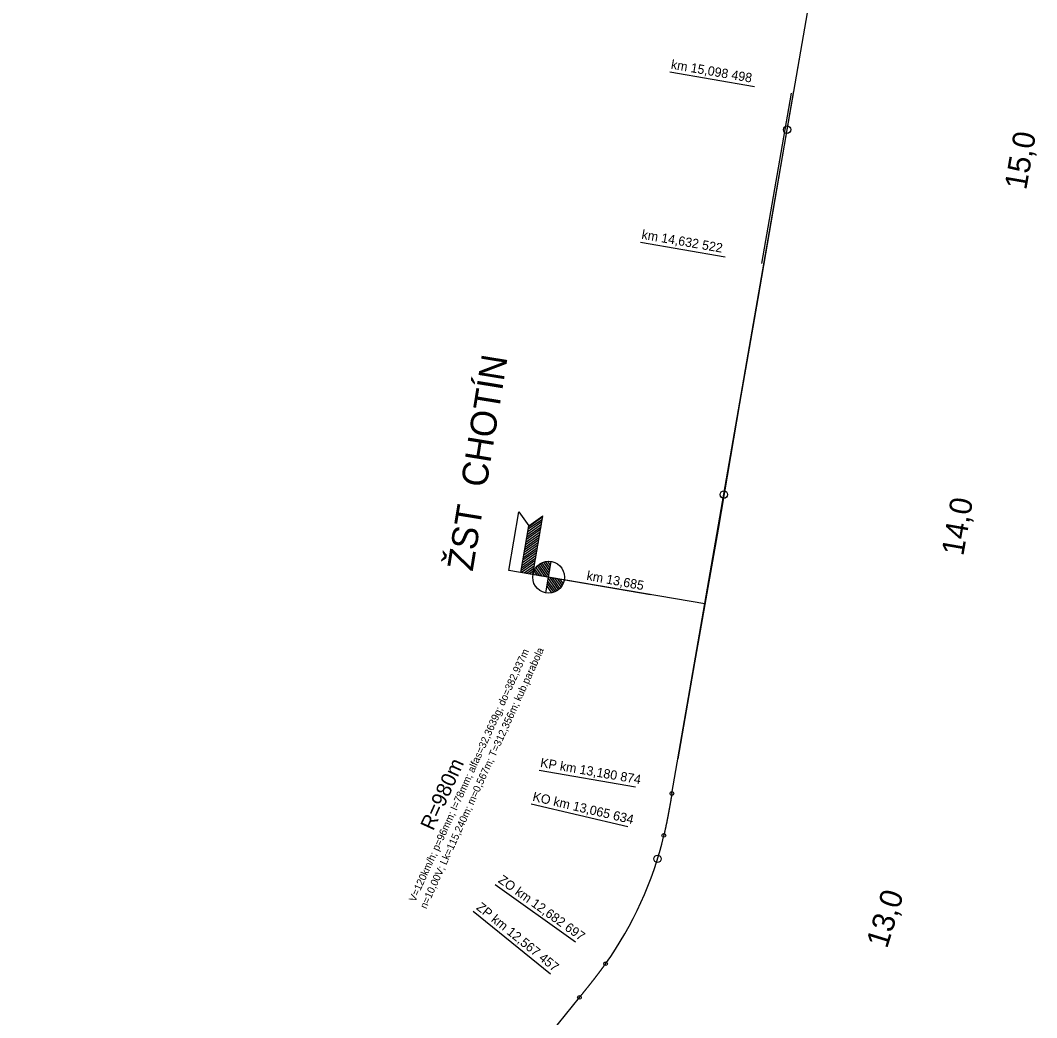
# Model space of a CAD drawing. Extents: x -504999 to -493096, y -1330712 to -1305226.
# Drawn here: x -498638 to -495893, y -1326629 to -1323937 of the extents above; entities that cross this region are included whole.
import ezdxf

# ---------------------------------------------------------------- set-up
doc = ezdxf.new("R2010")
doc.units = 0
for name, color, linetype in [('0_HM', 7, 'Continuous'), ('0_obluky', 7, 'Continuous'), ('0_popis oblukov', 7, 'Continuous'), ('0_STANICE', 7, 'Continuous'), ('0_stanicenie oblukov', 7, 'Continuous'), ('dotyčnice', 7, 'Continuous'), ('Level 1', 7, 'Continuous'), ('PHS', 7, 'Continuous')]:
    doc.layers.add(name, color=color, linetype=linetype)

msp = doc.modelspace()

# ---------------------------------------------------------------- linework, layer by layer
at = {"layer": '0_HM'}
for centre in [(-496567.3, -1324232), (-496738.3, -1325217.3), (-496917.3, -1326200.8)]:
    msp.add_circle(centre, 10, dxfattribs=at)
at = {"layer": '0_obluky'}
for p, q in [((-496878.3, -1326024.3), (-496328.8, -1322856.9)), ((-498638, -1328441.5), (-497128.1, -1326574.9))]:
    msp.add_line(p, q, dxfattribs=at)
for points in [[(-496878.3, -1326024.3), (-496878.5, -1326025.3), (-496878.6, -1326026.3), (-496878.8, -1326027.3), (-496879, -1326028.3), (-496879.1, -1326029.3), (-496879.3, -1326030.3), (-496879.5, -1326031.2), (-496879.7, -1326032.2), (-496879.8, -1326033.2), (-496880, -1326034.2), (-496880.2, -1326035.2), (-496880.3, -1326036.2), (-496880.5, -1326037.2), (-496880.7, -1326038.2), (-496880.9, -1326039.1), (-496881, -1326040.1), (-496881.2, -1326041.1), (-496881.4, -1326042.1), (-496881.6, -1326043.1), (-496881.7, -1326044.1), (-496881.9, -1326045.1), (-496882.1, -1326046.1), (-496882.2, -1326047), (-496882.4, -1326048), (-496882.6, -1326049), (-496882.8, -1326050), (-496882.9, -1326051), (-496883.1, -1326052), (-496883.3, -1326053), (-496883.5, -1326053.9), (-496883.6, -1326054.9), (-496883.8, -1326055.9), (-496884, -1326056.9), (-496884.2, -1326057.9), (-496884.3, -1326058.9), (-496884.5, -1326059.9), (-496884.7, -1326060.8), (-496884.9, -1326061.8), (-496885.1, -1326062.8), (-496885.2, -1326063.8), (-496885.4, -1326064.8), (-496885.6, -1326065.8), (-496885.8, -1326066.8), (-496885.9, -1326067.7), (-496886.1, -1326068.7), (-496886.3, -1326069.7), (-496886.5, -1326070.7), (-496886.7, -1326071.7), (-496886.9, -1326072.7), (-496887, -1326073.7), (-496887.2, -1326074.6), (-496887.4, -1326075.6), (-496887.6, -1326076.6), (-496887.8, -1326077.6), (-496887.9, -1326078.6), (-496888.1, -1326079.6), (-496888.3, -1326080.6), (-496888.5, -1326081.5), (-496888.7, -1326082.5), (-496888.9, -1326083.5), (-496889.1, -1326084.5), (-496889.3, -1326085.5), (-496889.4, -1326086.5), (-496889.6, -1326087.4), (-496889.8, -1326088.4), (-496890, -1326089.4), (-496890.2, -1326090.4), (-496890.4, -1326091.4), (-496890.6, -1326092.4), (-496890.8, -1326093.3), (-496891, -1326094.3), (-496891.2, -1326095.3), (-496891.4, -1326096.3), (-496891.6, -1326097.3), (-496891.7, -1326098.3), (-496891.9, -1326099.2), (-496892.1, -1326100.2), (-496892.3, -1326101.2), (-496892.5, -1326102.2), (-496892.7, -1326103.2), (-496892.9, -1326104.2), (-496893.1, -1326105.1), (-496893.3, -1326106.1), (-496893.5, -1326107.1), (-496893.7, -1326108.1), (-496893.9, -1326109.1), (-496894.1, -1326110), (-496894.4, -1326111), (-496894.6, -1326112), (-496894.8, -1326113), (-496895, -1326114), (-496895.2, -1326114.9), (-496895.4, -1326115.9), (-496895.6, -1326116.9), (-496895.8, -1326117.9), (-496896, -1326118.9), (-496896.2, -1326119.8), (-496896.4, -1326120.8), (-496896.7, -1326121.8), (-496896.9, -1326122.8), (-496897.1, -1326123.8), (-496897.3, -1326124.7), (-496897.5, -1326125.7), (-496897.7, -1326126.7), (-496898, -1326127.7), (-496898.2, -1326128.7), (-496898.4, -1326129.6), (-496898.6, -1326130.6), (-496898.8, -1326131.6), (-496899.1, -1326132.6), (-496899.3, -1326133.5), (-496899.5, -1326134.5), (-496899.8, -1326135.5), (-496900, -1326136.5), (-496900.2, -1326137.5)], [(-497128.1, -1326574.9), (-497127.5, -1326574.2), (-497126.9, -1326573.4), (-497126.2, -1326572.6), (-497125.6, -1326571.8), (-497125, -1326571.1), (-497124.3, -1326570.3), (-497123.7, -1326569.5), (-497123.1, -1326568.7), (-497122.5, -1326567.9), (-497121.8, -1326567.2), (-497121.2, -1326566.4), (-497120.6, -1326565.6), (-497119.9, -1326564.8), (-497119.3, -1326564), (-497118.7, -1326563.3), (-497118, -1326562.5), (-497117.4, -1326561.7), (-497116.8, -1326560.9), (-497116.2, -1326560.1), (-497115.5, -1326559.4), (-497114.9, -1326558.6), (-497114.3, -1326557.8), (-497113.6, -1326557), (-497113, -1326556.2), (-497112.4, -1326555.5), (-497111.8, -1326554.7), (-497111.1, -1326553.9), (-497110.5, -1326553.1), (-497109.9, -1326552.3), (-497109.3, -1326551.6), (-497108.6, -1326550.8), (-497108, -1326550), (-497107.4, -1326549.2), (-497106.7, -1326548.4), (-497106.1, -1326547.6), (-497105.5, -1326546.9), (-497104.9, -1326546.1), (-497104.2, -1326545.3), (-497103.6, -1326544.5), (-497103, -1326543.7), (-497102.4, -1326543), (-497101.7, -1326542.2), (-497101.1, -1326541.4), (-497100.5, -1326540.6), (-497099.9, -1326539.8), (-497099.3, -1326539), (-497098.6, -1326538.2), (-497098, -1326537.5), (-497097.4, -1326536.7), (-497096.8, -1326535.9), (-497096.1, -1326535.1), (-497095.5, -1326534.3), (-497094.9, -1326533.5), (-497094.3, -1326532.7), (-497093.7, -1326532), (-497093, -1326531.2), (-497092.4, -1326530.4), (-497091.8, -1326529.6), (-497091.2, -1326528.8), (-497090.6, -1326528), (-497090, -1326527.2), (-497089.3, -1326526.4), (-497088.7, -1326525.6), (-497088.1, -1326524.9), (-497087.5, -1326524.1), (-497086.9, -1326523.3), (-497086.3, -1326522.5), (-497085.6, -1326521.7), (-497085, -1326520.9), (-497084.4, -1326520.1), (-497083.8, -1326519.3), (-497083.2, -1326518.5), (-497082.6, -1326517.7), (-497082, -1326516.9), (-497081.4, -1326516.1), (-497080.8, -1326515.3), (-497080.1, -1326514.6), (-497079.5, -1326513.8), (-497078.9, -1326513), (-497078.3, -1326512.2), (-497077.7, -1326511.4), (-497077.1, -1326510.6), (-497076.5, -1326509.8), (-497075.9, -1326509), (-497075.3, -1326508.2), (-497074.7, -1326507.4), (-497074.1, -1326506.6), (-497073.5, -1326505.8), (-497072.9, -1326505), (-497072.3, -1326504.2), (-497071.7, -1326503.4), (-497071.1, -1326502.6), (-497070.5, -1326501.8), (-497069.9, -1326501), (-497069.3, -1326500.2), (-497068.7, -1326499.4), (-497068.1, -1326498.5), (-497067.5, -1326497.7), (-497066.9, -1326496.9), (-497066.3, -1326496.1), (-497065.7, -1326495.3), (-497065.1, -1326494.5), (-497064.5, -1326493.7), (-497063.9, -1326492.9), (-497063.3, -1326492.1), (-497062.7, -1326491.3), (-497062.1, -1326490.5), (-497061.5, -1326489.7), (-497061, -1326488.8), (-497060.4, -1326488), (-497059.8, -1326487.2), (-497059.2, -1326486.4), (-497058.6, -1326485.6), (-497058, -1326484.8), (-497057.4, -1326484)]]:
    msp.add_lwpolyline(points, dxfattribs=at)
for centre in [(-496878.3, -1326024.3), (-496900.2, -1326137.5), (-497057.4, -1326484), (-497128.1, -1326574.9)]:
    msp.add_circle(centre, 5, dxfattribs=at)
msp.add_arc((-497854.3, -1325913.5), 980, 324.3998, 346.7882, dxfattribs=at)
at = {"layer": '0_STANICE'}
for p, q in [((-497318.8, -1325421.9), (-497291.7, -1325263.6)), ((-497291.7, -1325263.6), (-497264.7, -1325301.7)), ((-497228.2, -1325284.1), (-497266.3, -1325311)), ((-497227, -1325277.1), (-497265.1, -1325304.1)), ((-497264.7, -1325301.7), (-497226.6, -1325274.7)), ((-497253.7, -1325433.1), (-497226.6, -1325274.7)), ((-497286.3, -1325427.5), (-497264.7, -1325301.7)), ((-497233, -1325311.9), (-497271.1, -1325338.9)), ((-497231.8, -1325305), (-497269.9, -1325331.9)), ((-497230.6, -1325298), (-497268.7, -1325325)), ((-497229.4, -1325291), (-497267.5, -1325318)), ((-497237.8, -1325339.8), (-497275.9, -1325366.8)), ((-497236.6, -1325332.8), (-497274.7, -1325359.8)), ((-497235.4, -1325325.9), (-497273.5, -1325352.8)), ((-497234.2, -1325318.9), (-497272.3, -1325345.9)), ((-497242.5, -1325367.7), (-497280.7, -1325394.7)), ((-497241.4, -1325360.7), (-497279.5, -1325387.7)), ((-497240.2, -1325353.8), (-497278.3, -1325380.7)), ((-497239, -1325346.8), (-497277.1, -1325373.8)), ((-497247.3, -1325395.6), (-497285.4, -1325422.5)), ((-497246.1, -1325388.6), (-497284.2, -1325415.6)), ((-497244.9, -1325381.6), (-497283, -1325408.6)), ((-497243.7, -1325374.7), (-497281.9, -1325401.6)), ((-496935.9, -1325487.5), (-497318.8, -1325421.9)), ((-497248.5, -1325402.5), (-497284.3, -1325427.9)), ((-497249.7, -1325409.5), (-497277.3, -1325429)), ((-497250.9, -1325416.5), (-497270.3, -1325430.2)), ((-497250.9, -1325416.5), (-497270.3, -1325430.2)), ((-497252.1, -1325423.5), (-497263.4, -1325431.4)), ((-497252.1, -1325423.5), (-497263.4, -1325431.4)), ((-497242.5, -1325435), (-497250.8, -1325423.2)), ((-497235.5, -1325436.2), (-497248.2, -1325418.2)), ((-497228.5, -1325437.4), (-497245.2, -1325413.8)), ((-497221.6, -1325438.6), (-497241.8, -1325410)), ((-497214.6, -1325439.8), (-497238.1, -1325406.6)), ((-497210.7, -1325436.6), (-497234, -1325403.7)), ((-497209.5, -1325429.6), (-497229.5, -1325401.4)), ((-497208.3, -1325422.7), (-497224.7, -1325399.5)), ((-497207.1, -1325415.7), (-497219.6, -1325398.1)), ((-497218.6, -1325482.7), (-497204.1, -1325397.9)), ((-497205.9, -1325408.7), (-497213.9, -1325397.4)), ((-497253.3, -1325430.4), (-497256.4, -1325432.6)), ((-497249.4, -1325433.8), (-497252.8, -1325429)), ((-496789.5, -1325512.6), (-497249.5, -1325433.8)), ((-497192.8, -1325479.2), (-497213.1, -1325450.6)), ((-497188.4, -1325476.8), (-497211.9, -1325443.6)), ((-497184.4, -1325473.8), (-497207.6, -1325441)), ((-497180.6, -1325470.5), (-497200.6, -1325442.2)), ((-497177.3, -1325466.6), (-497193.7, -1325443.4)), ((-497174.3, -1325462.2), (-497186.7, -1325444.6)), ((-497171.7, -1325457.1), (-497179.7, -1325445.8)), ((-497202.7, -1325482.5), (-497215.5, -1325464.5)), ((-497197.6, -1325481.1), (-497214.3, -1325457.5))]:
    msp.add_line(p, q, dxfattribs=at)
msp.add_circle((-497211.3, -1325440.3), 43, dxfattribs=at)
at = {"layer": '0_stanicenie oblukov'}
for p, q in [((-496976.8, -1326007.2), (-497237, -1325962.1)), ((-496997.6, -1326114.6), (-497258.6, -1326053.3)), ((-497138.7, -1326425.7), (-497355.4, -1326270.6)), ((-497205.9, -1326512.1), (-497415, -1326342.9))]:
    msp.add_line(p, q, dxfattribs=at)
at = {"layer": 'dotyčnice'}
msp.add_line((-496862.1, -1325930.8), (-496292.9, -1322649.9), dxfattribs=at)
at = {"layer": 'Level 1'}
msp.add_lwpolyline([(-496549.9, -1324127.4), (-496646.5, -1324687.4), (-496695.5, -1324971.3), (-496753.9, -1325310.2), (-496817.3, -1325671.8), (-496862.1, -1325930.8)], dxfattribs=at)
at = {"layer": 'PHS'}
for p, q in [((-496654.9, -1324116.8), (-496883.9, -1324077.1)), ((-496556.4, -1324133.9), (-496636.1, -1324593)), ((-496734.6, -1324575.9), (-496963.3, -1324536.3))]:
    msp.add_line(p, q, dxfattribs=at)

# ---------------------------------------------------------------- texts
at = {"layer": '0_HM'}
for s, rotation, p in [('15,0', 80.1577, (-495921.6, -1324396.7)), ('14,0', 80.1577, (-496091.6, -1325384.8)), ('13,0', 72.9509, (-496297.5, -1326444.8))]:
    msp.add_text(s, height=60, rotation=rotation, dxfattribs=at).set_placement(p)
at = {"layer": '0_popis oblukov'}
for s, height, p in [('V=120km/h; p=96mm; I=78mm; alfas=32,3639g; do=382,937m', 20, (-497571.5, -1326318.5)), ('n=10,00V; Lk=115,240m; m=0,567m; T=312,356m; kub.parabola', 20, (-497541.6, -1326337.2)), ('R=980m', 40, (-497522.9, -1326126.7))]:
    msp.add_text(s, height=height, rotation=65.594, dxfattribs=at).set_placement(p)
at = {"layer": '0_STANICE'}
for s, height, rotation, p in [('ŽST  CHOTÍN', 70, 80.7348, (-497416.5, -1325426.2)), ('km 13,685', 25, 349.5961, (-497110.1, -1325447.3))]:
    msp.add_text(s, height=height, rotation=rotation, dxfattribs=at).set_placement(p)
at = {"layer": '0_stanicenie oblukov'}
for s, rotation, p in [('KP km 13,180 874', 350.1577, (-497235.3, -1325952.3)), ('KO km 13,065 634', 346.7882, (-497256.3, -1326043.6)), ('ZO km 12,682 697', 324.3998, (-497349.6, -1326262.5)), ('ZP km 12,567 457', 321.0302, (-497408.7, -1326335.2))]:
    msp.add_text(s, height=25, rotation=rotation, dxfattribs=at).set_placement(p)
at = {"layer": 'PHS'}
for s, p in [('km 15,098 498', (-496882.2, -1324067.2)), ('km 14,632 522', (-496961.6, -1324526.4))]:
    msp.add_text(s, height=25, rotation=350.1577, dxfattribs=at).set_placement(p)

doc.saveas('drawing.dxf')
